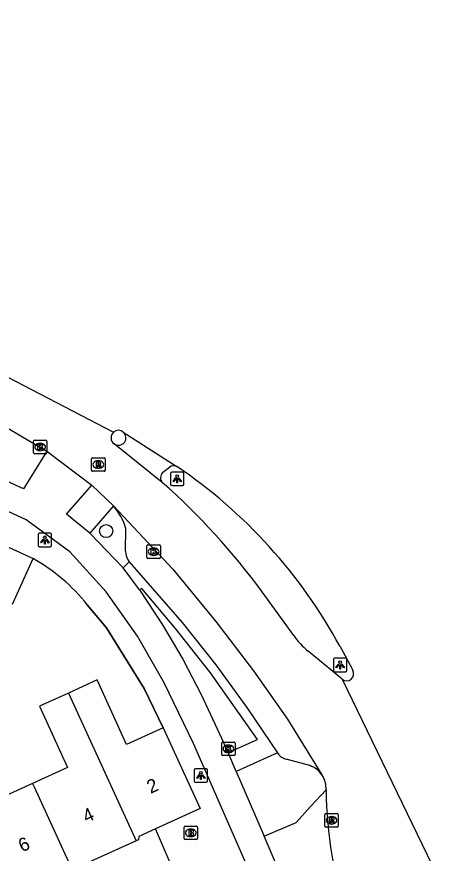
# Model space of a CAD drawing. Extents: x 161845 to 162341, y 381620 to 382158.
# Drawn here: x 162271.1 to 162302.8, y 381756.3 to 381818.5 of the extents above; entities that cross this region are included whole.
import ezdxf

# ---------------------------------------------------------------- set-up
doc = ezdxf.new("R2010")
doc.units = 0
for name, color, linetype in [('IMGEO_Boom', 7, 'Continuous'), ('IMGEO_Brandkraan', 7, 'Continuous'), ('IMGEO_Kolk', 7, 'Continuous'), ('IMGEO_Lichtpunt', 7, 'Continuous'), ('IMGEO_Muur', 7, 'Continuous'), ('IMGEO_Pand', 7, 'Continuous'), ('IMGEO_Pand_nummerreeks', 7, 'Continuous'), ('IMGEO_Parkeervlak_open', 7, 'Continuous'), ('IMGEO_Rijbaan_lokaal_gesloten', 7, 'Continuous'), ('IMGEO_Rioolput', 7, 'Continuous'), ('IMGEO_Verkeerseiland_open', 7, 'Continuous'), ('IMGEO_Voetpad_gesloten', 7, 'Continuous'), ('IMGEO_Voetpad_open', 7, 'Continuous')]:
    doc.layers.add(name, color=color, linetype=linetype)

msp = doc.modelspace()

# ---------------------------------------------------------------- linework, layer by layer
at = {"layer": 'IMGEO_Boom'}
msp.add_circle((162277.76, 381780.26), 0.489, dxfattribs=at)
at = {"layer": 'IMGEO_Brandkraan'}
for p, q in [((162283.553, 381757.394), (162283.553, 381758.246)), ((162283.628, 381758.32), (162284.48, 381758.32)), ((162284.554, 381758.246), (162284.554, 381757.394)), ((162284.064, 381757.54), (162284.039, 381757.54)), ((162284.041, 381758.1), (162284.066, 381758.1)), ((162284.48, 381757.32), (162283.628, 381757.32))]:
    msp.add_line(p, q, dxfattribs=at)
for points in [[(162283.553, 381757.394), (162283.553, 381758.246)], [(162283.628, 381758.32), (162284.48, 381758.32)], [(162284.554, 381758.246), (162284.554, 381757.394)], [(162283.901, 381758.02), (162283.901, 381757.62), (162284.114, 381757.62)], [(162284.132, 381758.02), (162283.901, 381758.02)], [(162284.08, 381757.939), (162284.026, 381757.939), (162284.026, 381757.863)], [(162284.026, 381757.863), (162284.079, 381757.863)], [(162284.088, 381757.787), (162284.026, 381757.787), (162284.026, 381757.706)], [(162284.026, 381757.706), (162284.088, 381757.706)], [(162284.48, 381757.32), (162283.628, 381757.32)]]:
    msp.add_lwpolyline(points, dxfattribs=at)
for centre, radius, start, end in [((162283.63, 381758.244), 0.0765, 91.55205, 178.44795), ((162283.63, 381758.244), 0.0765, 91.55205, 178.44795), ((162284.478, 381758.244), 0.0765, 1.55205, 88.44795), ((162284.478, 381758.244), 0.0765, 1.55205, 88.44795), ((162284.081, 381757.901), 0.0379, 267.82845, 90.93552), ((162284.089, 381757.746), 0.0404, 269.87594, 90.50774), ((162284.12, 381757.871), 0.251, 268.66757, 293.53466), ((162284.136, 381757.875), 0.145, 59.4692, 91.53667), ((162284.161, 381757.922), 0.0922, 285.51372, 58.15012), ((162284.166, 381757.73), 0.105, 301.31148, 78.98903), ((162283.63, 381757.396), 0.0765, 181.55205, 268.44795), ((162283.63, 381757.396), 0.0765, 181.55205, 268.44795), ((162284.478, 381757.396), 0.0765, 271.55205, 358.44795), ((162284.478, 381757.396), 0.0765, 271.55205, 358.44795)]:
    msp.add_arc(centre, radius, start, end, dxfattribs=at)
for centre, major_axis, ratio, start_param, end_param in [((162284.04, 381757.82), (-0.387, 0.002), 0.722429, 4.712389, 7.853982), ((162284.065, 381757.82), (-0.39, 0.002), 0.717154, 1.570796, 4.712389)]:
    msp.add_ellipse(centre, major_axis=major_axis, ratio=ratio, start_param=start_param, end_param=end_param, dxfattribs=at)
at = {"layer": 'IMGEO_Kolk'}
for p, q in [((162272.355, 381786.085), (162272.355, 381786.937)), ((162272.43, 381787.011), (162273.282, 381787.011)), ((162272.843, 381786.791), (162272.868, 381786.791)), ((162273.356, 381786.937), (162273.356, 381786.085)), ((162272.866, 381786.231), (162272.841, 381786.231)), ((162273.282, 381786.011), (162272.43, 381786.011)), ((162280.79, 381778.304), (162280.79, 381779.156)), ((162280.865, 381779.23), (162281.717, 381779.23)), ((162281.278, 381779.01), (162281.303, 381779.01)), ((162281.791, 381779.156), (162281.791, 381778.304)), ((162281.717, 381778.23), (162280.865, 381778.23)), ((162281.301, 381778.45), (162281.276, 381778.45)), ((162286.351, 381763.646), (162286.351, 381764.498)), ((162286.426, 381764.572), (162287.278, 381764.572)), ((162286.839, 381764.352), (162286.864, 381764.352)), ((162287.352, 381764.498), (162287.352, 381763.646)), ((162286.862, 381763.792), (162286.837, 381763.792)), ((162287.278, 381763.572), (162286.426, 381763.572))]:
    msp.add_line(p, q, dxfattribs=at)
for points in [[(162272.355, 381786.085), (162272.355, 381786.937)], [(162272.43, 381787.011), (162273.282, 381787.011)], [(162273.356, 381786.937), (162273.356, 381786.085)], [(162272.676, 381786.711), (162272.799, 381786.711), (162272.799, 381786.56), (162272.929, 381786.711), (162273.093, 381786.711), (162272.947, 381786.56), (162273.1, 381786.311), (162272.948, 381786.311), (162272.863, 381786.475), (162272.799, 381786.408), (162272.799, 381786.311), (162272.676, 381786.311), (162272.676, 381786.711)], [(162273.282, 381786.011), (162272.43, 381786.011)], [(162280.79, 381778.304), (162280.79, 381779.156)], [(162280.865, 381779.23), (162281.717, 381779.23)], [(162281.111, 381778.93), (162281.234, 381778.93), (162281.234, 381778.779), (162281.364, 381778.93), (162281.528, 381778.93), (162281.382, 381778.779), (162281.535, 381778.53), (162281.383, 381778.53), (162281.298, 381778.694), (162281.234, 381778.627), (162281.234, 381778.53), (162281.111, 381778.53), (162281.111, 381778.93)], [(162281.791, 381779.156), (162281.791, 381778.304)], [(162281.717, 381778.23), (162280.865, 381778.23)], [(162286.351, 381763.646), (162286.351, 381764.498)], [(162286.426, 381764.572), (162287.278, 381764.572)], [(162287.352, 381764.498), (162287.352, 381763.646)], [(162286.672, 381764.272), (162286.795, 381764.272), (162286.795, 381764.121), (162286.925, 381764.272), (162287.089, 381764.272), (162286.943, 381764.121), (162287.096, 381763.872), (162286.944, 381763.872), (162286.859, 381764.036), (162286.795, 381763.969), (162286.795, 381763.872), (162286.672, 381763.872), (162286.672, 381764.272)], [(162287.278, 381763.572), (162286.426, 381763.572)]]:
    msp.add_lwpolyline(points, dxfattribs=at)
for centre, start, end in [((162272.432, 381786.935), 91.55205, 178.44795), ((162272.432, 381786.935), 91.55205, 178.44795), ((162273.28, 381786.935), 1.55205, 88.44795), ((162273.28, 381786.935), 1.55205, 88.44795), ((162272.432, 381786.087), 181.55205, 268.44795), ((162272.432, 381786.087), 181.55205, 268.44795), ((162273.28, 381786.087), 271.55205, 358.44795), ((162273.28, 381786.087), 271.55205, 358.44795), ((162280.867, 381779.154), 91.55205, 178.44795), ((162280.867, 381779.154), 91.55205, 178.44795), ((162281.715, 381779.154), 1.55205, 88.44795), ((162281.715, 381779.154), 1.55205, 88.44795), ((162280.867, 381778.306), 181.55205, 268.44795), ((162280.867, 381778.306), 181.55205, 268.44795), ((162281.715, 381778.306), 271.55205, 358.44795), ((162281.715, 381778.306), 271.55205, 358.44795), ((162286.428, 381764.496), 91.55205, 178.44795), ((162286.428, 381764.496), 91.55205, 178.44795), ((162287.276, 381764.496), 1.55205, 88.44795), ((162287.276, 381764.496), 1.55205, 88.44795), ((162286.428, 381763.648), 181.55205, 268.44795), ((162286.428, 381763.648), 181.55205, 268.44795), ((162287.276, 381763.648), 271.55205, 358.44795), ((162287.276, 381763.648), 271.55205, 358.44795)]:
    msp.add_arc(centre, 0.0765, start, end, dxfattribs=at)
for centre, major_axis, ratio, start_param, end_param in [((162272.842, 381786.511), (-0.387, 0.002), 0.722429, 4.712389, 7.853982), ((162272.867, 381786.511), (-0.39, 0.002), 0.717154, 1.570796, 4.712389), ((162281.277, 381778.73), (-0.387, 0.002), 0.722429, 4.712389, 7.853982), ((162281.302, 381778.73), (-0.39, 0.002), 0.717154, 1.570796, 4.712389), ((162286.838, 381764.072), (-0.387, 0.002), 0.722429, 4.712389, 7.853982), ((162286.863, 381764.072), (-0.39, 0.002), 0.717154, 1.570796, 4.712389)]:
    msp.add_ellipse(centre, major_axis=major_axis, ratio=ratio, start_param=start_param, end_param=end_param, dxfattribs=at)
at = {"layer": 'IMGEO_Lichtpunt'}
for p, q in [((162282.553, 381784.543), (162282.553, 381783.736)), ((162282.553, 381784.543), (162282.553, 381783.736)), ((162283.455, 381784.638), (162282.647, 381784.638)), ((162283.455, 381784.638), (162282.647, 381784.638)), ((162283.549, 381783.736), (162283.549, 381784.543)), ((162283.549, 381783.736), (162283.549, 381784.543)), ((162282.647, 381783.642), (162283.455, 381783.642)), ((162282.647, 381783.642), (162283.455, 381783.642)), ((162272.708, 381780), (162272.708, 381779.193)), ((162272.708, 381780), (162272.708, 381779.193)), ((162273.61, 381780.095), (162272.802, 381780.095)), ((162273.61, 381780.095), (162272.802, 381780.095)), ((162273.704, 381779.193), (162273.704, 381780)), ((162273.704, 381779.193), (162273.704, 381780)), ((162272.802, 381779.099), (162273.61, 381779.099)), ((162272.802, 381779.099), (162273.61, 381779.099)), ((162294.659, 381770.706), (162294.659, 381769.899)), ((162294.659, 381770.706), (162294.659, 381769.899)), ((162295.561, 381770.801), (162294.753, 381770.801)), ((162295.561, 381770.801), (162294.753, 381770.801)), ((162295.655, 381769.899), (162295.655, 381770.706)), ((162295.655, 381769.899), (162295.655, 381770.706)), ((162294.753, 381769.805), (162295.561, 381769.805)), ((162294.753, 381769.805), (162295.561, 381769.805)), ((162284.311, 381762.483), (162284.311, 381761.676)), ((162284.311, 381762.483), (162284.311, 381761.676)), ((162285.213, 381762.578), (162284.405, 381762.578)), ((162285.213, 381762.578), (162284.405, 381762.578)), ((162285.307, 381761.676), (162285.307, 381762.483)), ((162285.307, 381761.676), (162285.307, 381762.483)), ((162284.405, 381761.582), (162285.213, 381761.582)), ((162284.405, 381761.582), (162285.213, 381761.582))]:
    msp.add_line(p, q, dxfattribs=at)
for points in [[(162282.927, 381784.207), (162282.966, 381784.179), (162282.778, 381783.917), (162282.74, 381783.944), (162282.927, 381784.207)], [(162283.029, 381784.159), (162283.076, 381784.159), (162283.076, 381783.837), (162283.029, 381783.837), (162283.029, 381784.159)], [(162283.139, 381784.179), (162283.177, 381784.206), (162283.364, 381783.944), (162283.325, 381783.916), (162283.139, 381784.179)], [(162273.082, 381779.664), (162273.121, 381779.636), (162272.933, 381779.374), (162272.895, 381779.401), (162273.082, 381779.664)], [(162273.184, 381779.616), (162273.231, 381779.616), (162273.231, 381779.294), (162273.184, 381779.294), (162273.184, 381779.616)], [(162273.294, 381779.636), (162273.332, 381779.663), (162273.519, 381779.401), (162273.48, 381779.373), (162273.294, 381779.636)], [(162295.033, 381770.37), (162295.072, 381770.342), (162294.884, 381770.08), (162294.846, 381770.107), (162295.033, 381770.37)], [(162295.135, 381770.322), (162295.182, 381770.322), (162295.182, 381770), (162295.135, 381770), (162295.135, 381770.322)], [(162295.245, 381770.342), (162295.283, 381770.369), (162295.47, 381770.107), (162295.431, 381770.079), (162295.245, 381770.342)], [(162284.685, 381762.147), (162284.724, 381762.119), (162284.536, 381761.857), (162284.498, 381761.884), (162284.685, 381762.147)], [(162284.787, 381762.099), (162284.834, 381762.099), (162284.834, 381761.777), (162284.787, 381761.777), (162284.787, 381762.099)], [(162284.897, 381762.119), (162284.935, 381762.146), (162285.122, 381761.884), (162285.083, 381761.856), (162284.897, 381762.119)]]:
    msp.add_lwpolyline(points, dxfattribs=at)
for centre in [(162283.052, 381784.341), (162273.207, 381779.798), (162295.158, 381770.504), (162284.81, 381762.281)]:
    msp.add_circle(centre, 0.0994, dxfattribs=at)
for centre, start, end in [((162282.647, 381784.543), 90, 180), ((162282.647, 381784.543), 90, 180), ((162283.455, 381784.543), 0, 90), ((162283.455, 381784.543), 0, 90), ((162282.647, 381783.736), 180, 270), ((162282.647, 381783.736), 180, 270), ((162283.455, 381783.736), 270, 0), ((162283.455, 381783.736), 270, 360), ((162272.802, 381780), 90, 180), ((162272.802, 381780), 90, 180), ((162273.61, 381780), 0, 90), ((162273.61, 381780), 0, 90), ((162272.802, 381779.193), 180, 270), ((162272.802, 381779.193), 180, 270), ((162273.61, 381779.193), 270, 0), ((162273.61, 381779.193), 270, 360), ((162294.753, 381770.706), 90, 180), ((162294.753, 381770.706), 90, 180), ((162295.561, 381770.706), 0, 90), ((162295.561, 381770.706), 0, 90), ((162294.753, 381769.899), 180, 270), ((162294.753, 381769.899), 180, 270), ((162295.561, 381769.899), 270, 0), ((162295.561, 381769.899), 270, 360), ((162284.405, 381762.483), 90, 180), ((162284.405, 381762.483), 90, 180), ((162285.213, 381762.483), 0, 90), ((162285.213, 381762.483), 0, 90), ((162284.405, 381761.676), 180, 270), ((162284.405, 381761.676), 180, 270), ((162285.213, 381761.676), 270, 0), ((162285.213, 381761.676), 270, 360)]:
    msp.add_arc(centre, 0.0946, start, end, dxfattribs=at)
at = {"layer": 'IMGEO_Muur'}
msp.add_lwpolyline([(162282.012, 381765.641), (162280.601, 381768.553), (162277.781, 381773.055), (162276.358, 381774.78)], dxfattribs=at)
msp.add_arc((162265.362, 381766.004), 14.069, 38.59496, 60.32198, dxfattribs=at)
at = {"layer": 'IMGEO_Pand'}
for points in [[(162269.84, 381779.353), (162272.328, 381778.227)], [(162270.79, 381774.833), (162272.328, 381778.227)], [(162282.012, 381765.641), (162279.286, 381764.396), (162277.096, 381769.191), (162274.96, 381768.215)], [(162274.96, 381768.215), (162272.802, 381767.23), (162274.881, 381762.678), (162272.292, 381761.495)], [(162274.96, 381768.215), (162279.982, 381757.228)], [(162282.012, 381765.641), (162284.758, 381759.63), (162281.432, 381758.111)], [(162272.292, 381761.495), (162270.053, 381760.473), (162267.923, 381765.137), (162265.401, 381763.985)], [(162272.292, 381761.495), (162272.402, 381761.254), (162275.235, 381755.059)], [(162281.432, 381758.111), (162280.189, 381757.543), (162280.166, 381757.312), (162279.982, 381757.228)], [(162279.982, 381757.228), (162275.235, 381755.059)]]:
    msp.add_lwpolyline(points, dxfattribs=at)
at = {"layer": 'IMGEO_Parkeervlak_open'}
for points in [[(162279.197, 381778.777), (162279.235, 381780.454)], [(162292.898, 381762.818), (162291.154, 381763.302)]]:
    msp.add_lwpolyline(points, dxfattribs=at)
for centre, radius, start, end in [((162274.478, 381778.958), 4.986, 17.45711, 39.60627), ((162280.501, 381778.783), 1.304, 180.28188, 217.96443), ((162291.365, 381764.292), 1.012, 210.98439, 257.97326), ((162292.325, 381761.122), 1.79, 34.08019, 71.33847)]:
    msp.add_arc(centre, radius, start, end, dxfattribs=at)
at = {"layer": 'IMGEO_Rijbaan_lokaal_gesloten'}
for points in [[(162270.414, 381791.728), (162278.312, 381787.616)], [(162269.159, 381788.667), (162273.356, 381786.194)], [(162279.038, 381787.612), (162283.019, 381785.067)], [(162281.936, 381783.879), (162278.362, 381786.75)], [(162273.356, 381786.194), (162276.701, 381783.665)], [(162276.701, 381783.665), (162278.32, 381782.137)], [(162278.32, 381782.137), (162282.721, 381777.43), (162285.929, 381773.537), (162288.729, 381769.86), (162291.248, 381766.267), (162293.808, 381762.125)], [(162291.706, 381772.503), (162289.369, 381775.736)], [(162295.318, 381769.244), (162292.781, 381771.328)], [(162295.151, 381771.682), (162296.096, 381769.905)], [(162295.318, 381769.244), (162302.75, 381753.874)]]:
    msp.add_lwpolyline(points, dxfattribs=at)
for centre, radius, start, end in [((162278.673, 381787.202), 0.549, 131.0849, 235.5239), ((162278.673, 381787.202), 0.549, 48.32987, 131.03878), ((162261.572, 381753.437), 38.215, 28.51695, 55.8606), ((162247.28, 381744.78), 52.247, 36.33348, 48.44671), ((162296.355, 381775.677), 5.629, 214.32265, 230.58774), ((162295.648, 381769.644), 0.519, 230.47063, 30.23278), ((162292.331, 381761.126), 1.783, 356.22586, 34.05836), ((162326.441, 381761.439), 32.333, 180.76204, 198.03065)]:
    msp.add_arc(centre, radius, start, end, dxfattribs=at)
at = {"layer": 'IMGEO_Rioolput'}
for p, q in [((162276.681, 381784.779), (162276.681, 381785.631)), ((162276.756, 381785.705), (162277.608, 381785.705)), ((162277.682, 381785.631), (162277.682, 381784.779)), ((162277.192, 381784.925), (162277.167, 381784.925)), ((162277.169, 381785.485), (162277.194, 381785.485)), ((162277.608, 381784.705), (162276.756, 381784.705)), ((162294.019, 381758.327), (162294.019, 381759.179)), ((162294.094, 381759.253), (162294.946, 381759.253)), ((162294.507, 381759.033), (162294.532, 381759.033)), ((162295.02, 381759.179), (162295.02, 381758.327)), ((162294.946, 381758.253), (162294.094, 381758.253)), ((162294.53, 381758.473), (162294.505, 381758.473))]:
    msp.add_line(p, q, dxfattribs=at)
for points in [[(162276.681, 381784.779), (162276.681, 381785.631)], [(162276.756, 381785.705), (162277.608, 381785.705)], [(162277.682, 381785.631), (162277.682, 381784.779)], [(162277.27, 381785.403), (162277.018, 381785.405), (162277.018, 381785.005)], [(162277.018, 381785.005), (162277.142, 381785.005), (162277.142, 381785.167), (162277.153, 381785.167)], [(162277.196, 381785.324), (162277.142, 381785.324), (162277.142, 381785.243)], [(162277.142, 381785.243), (162277.194, 381785.243)], [(162277.2, 381785.138), (162277.271, 381785.005), (162277.411, 381785.005), (162277.346, 381785.131)], [(162277.608, 381784.705), (162276.756, 381784.705)], [(162294.019, 381758.327), (162294.019, 381759.179)], [(162294.094, 381759.253), (162294.946, 381759.253)], [(162294.608, 381758.951), (162294.356, 381758.953), (162294.356, 381758.553)], [(162294.534, 381758.872), (162294.48, 381758.872), (162294.48, 381758.791)], [(162294.48, 381758.791), (162294.532, 381758.791)], [(162295.02, 381759.179), (162295.02, 381758.327)], [(162294.946, 381758.253), (162294.094, 381758.253)], [(162294.356, 381758.553), (162294.48, 381758.553), (162294.48, 381758.715), (162294.491, 381758.715)], [(162294.538, 381758.686), (162294.609, 381758.553), (162294.749, 381758.553), (162294.684, 381758.679)]]:
    msp.add_lwpolyline(points, dxfattribs=at)
for centre, radius, start, end in [((162276.758, 381785.629), 0.0765, 91.55205, 178.44795), ((162276.758, 381785.629), 0.0765, 91.55205, 178.44795), ((162277.606, 381785.629), 0.0765, 1.55205, 88.44795), ((162277.606, 381785.629), 0.0765, 1.55205, 88.44795), ((162277.152, 381785.114), 0.0533, 26.02933, 88.69889), ((162277.178, 381785.432), 0.19, 274.7715, 282.96867), ((162277.202, 381785.228), 0.0964, 77.00612, 93.18647), ((162277.216, 381785.285), 0.0378, 276.66336, 79.67722), ((162277.269, 381785.293), 0.109, 350.36119, 89.41601), ((162277.267, 381785.293), 0.112, 277.58423, 350.98172), ((162277.251, 381785.078), 0.108, 29.51342, 73.79051), ((162276.758, 381784.781), 0.0765, 181.55205, 268.44795), ((162276.758, 381784.781), 0.0765, 181.55205, 268.44795), ((162277.606, 381784.781), 0.0765, 271.55205, 358.44795), ((162277.606, 381784.781), 0.0765, 271.55205, 358.44795), ((162294.096, 381759.177), 0.0765, 91.55205, 178.44795), ((162294.096, 381759.177), 0.0765, 91.55205, 178.44795), ((162294.516, 381758.98), 0.19, 274.7715, 282.96867), ((162294.54, 381758.776), 0.0964, 77.00612, 93.18647), ((162294.554, 381758.833), 0.0378, 276.66336, 79.67722), ((162294.607, 381758.841), 0.109, 350.36119, 89.41601), ((162294.605, 381758.841), 0.112, 277.58423, 350.98172), ((162294.944, 381759.177), 0.0765, 1.55205, 88.44795), ((162294.944, 381759.177), 0.0765, 1.55205, 88.44795), ((162294.096, 381758.329), 0.0765, 181.55205, 268.44795), ((162294.096, 381758.329), 0.0765, 181.55205, 268.44795), ((162294.49, 381758.662), 0.0533, 26.02933, 88.69889), ((162294.589, 381758.626), 0.108, 29.51342, 73.79051), ((162294.944, 381758.329), 0.0765, 271.55205, 358.44795), ((162294.944, 381758.329), 0.0765, 271.55205, 358.44795)]:
    msp.add_arc(centre, radius, start, end, dxfattribs=at)
for centre, major_axis, ratio, start_param, end_param in [((162277.168, 381785.205), (-0.387, 0.002), 0.722429, 4.712389, 7.853982), ((162277.193, 381785.205), (-0.39, 0.002), 0.717154, 1.570796, 4.712389), ((162294.506, 381758.753), (-0.387, 0.002), 0.722429, 4.712389, 7.853982), ((162294.531, 381758.753), (-0.39, 0.002), 0.717154, 1.570796, 4.712389)]:
    msp.add_ellipse(centre, major_axis=major_axis, ratio=ratio, start_param=start_param, end_param=end_param, dxfattribs=at)
at = {"layer": 'IMGEO_Verkeerseiland_open'}
msp.add_lwpolyline([(162281.957, 381784.618), (162282.465, 381785.01)], dxfattribs=at)
for centre, radius, start, end in [((162278.686, 381787.192), 0.548, 233.75563, 50.03568), ((162282.785, 381784.621), 0.504, 62.3083, 129.44047), ((162282.362, 381784.237), 0.556, 136.73034, 220.01421)]:
    msp.add_arc(centre, radius, start, end, dxfattribs=at)
at = {"layer": 'IMGEO_Voetpad_gesloten'}
for points in [[(162289.497, 381752.523), (162284.268, 381764.473), (162282.076, 381768.974), (162280.091, 381772.447), (162277.759, 381775.733), (162275.072, 381778.709), (162271.828, 381781.089), (162266.754, 381783.434), (162197.313, 381814.891), (162168.761, 381826.912), (162165.238, 381828.801), (162160.086, 381831.935), (162154.18, 381835.7), (162147.552, 381840.181), (162140.263, 381845.513), (162134.882, 381849.978)], [(162273.356, 381786.194), (162271.63, 381783.405), (162262.003, 381787.815)], [(162276.556, 381780.102), (162274.816, 381781.511), (162276.701, 381783.665)], [(162276.556, 381780.102), (162279.031, 381777.525)], [(162280.238, 381775.879), (162279.031, 381777.525)], [(162280.238, 381775.879), (162281.96, 381773.297), (162283.451, 381770.742), (162284.848, 381768.06), (162286.825, 381763.803)], [(162287.421, 381762.394), (162286.825, 381763.803)], [(162287.421, 381762.394), (162289.504, 381757.563)], [(162293.643, 381747.456), (162291.289, 381753.398), (162289.504, 381757.563)]]:
    msp.add_lwpolyline(points, dxfattribs=at)
at = {"layer": 'IMGEO_Voetpad_open'}
for points in [[(162278.32, 381782.137), (162276.556, 381780.102)], [(162279.031, 381777.525), (162279.473, 381777.981)], [(162279.473, 381777.981), (162283.411, 381773.471), (162285.912, 381770.323), (162288.266, 381767.079), (162290.497, 381763.771)], [(162286.825, 381763.803), (162289.022, 381764.764), (162285.512, 381769.728), (162282.909, 381773.006), (162280.411, 381775.98), (162280.238, 381775.879)], [(162276.358, 381774.78), (162277.781, 381773.055), (162280.601, 381768.553), (162282.012, 381765.641)], [(162290.497, 381763.771), (162287.421, 381762.394)], [(162289.504, 381757.563), (162291.89, 381758.597), (162292.955, 381759.774), (162294.11, 381761.009)], [(162282.997, 381754.511), (162281.432, 381758.111)]]:
    msp.add_lwpolyline(points, dxfattribs=at)
msp.add_arc((162265.362, 381766.004), 14.069, 38.59496, 60.32198, dxfattribs=at)

# ---------------------------------------------------------------- texts
at = {"layer": 'IMGEO_Pand_nummerreeks'}
for s, rotation, p in [('2', 24.53405, (162281.071, 381760.717)), ('4', 24.53144, (162276.296, 381758.538)), ('6', 24.53144, (162271.519, 381756.358))]:
    msp.add_text(s, height=1, rotation=rotation, dxfattribs=at).set_placement(p)

doc.saveas('drawing.dxf')
